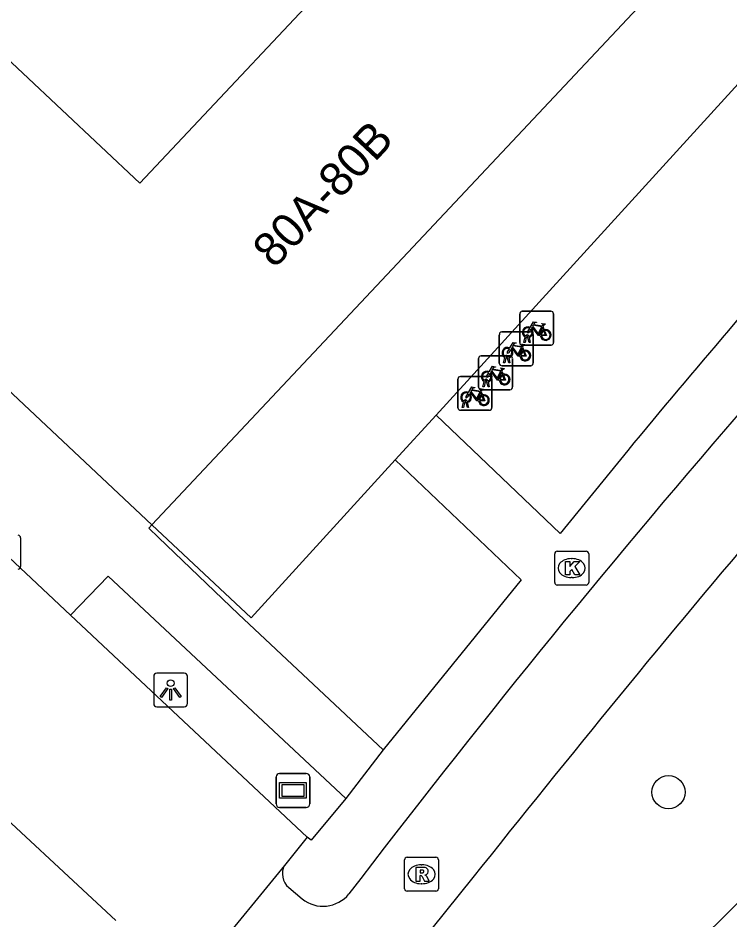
# Model space of a CAD drawing. Extents: x 159040 to 160094, y 381214 to 382518.
# Drawn here: x 159467.3 to 159488.3, y 381527.19 to 381553.81 of the extents above; entities that cross this region are included whole.
import ezdxf

# ---------------------------------------------------------------- set-up
doc = ezdxf.new("R2010")
doc.units = 0
for name, color, linetype in [('IMGEO_Boom', 7, 'Continuous'), ('IMGEO_Fietsenrek', 7, 'Continuous'), ('IMGEO_Fietspad_gesloten', 7, 'Continuous'), ('IMGEO_Groenvoorziening', 7, 'Continuous'), ('IMGEO_Kolk', 7, 'Continuous'), ('IMGEO_Lichtpunt', 7, 'Continuous'), ('IMGEO_Pand', 7, 'Continuous'), ('IMGEO_Pand_nummerreeks', 7, 'Continuous'), ('IMGEO_Rijbaan_lokaal_open', 7, 'Continuous'), ('IMGEO_Rijbaan_regionaal_gesloten', 7, 'Continuous'), ('IMGEO_Rioolput', 7, 'Continuous'), ('IMGEO_Straatnaambord', 7, 'Continuous'), ('IMGEO_Voetpad_open', 7, 'Continuous')]:
    doc.layers.add(name, color=color, linetype=linetype)

msp = doc.modelspace()

# ---------------------------------------------------------------- linework, layer by layer
at = {"layer": 'IMGEO_Boom'}
msp.add_circle((159486.484, 381530.962), 0.489, dxfattribs=at)
at = {"layer": 'IMGEO_Fietsenrek'}
for p, q in [((159482.094, 381544.228), (159482.094, 381545.069)), ((159482.094, 381545.069), (159482.094, 381544.228)), ((159482.169, 381545.153), (159483.01, 381545.153)), ((159483.01, 381545.153), (159482.169, 381545.153)), ((159483.094, 381545.078), (159483.094, 381544.237)), ((159483.094, 381544.237), (159483.094, 381545.078)), ((159482.781, 381544.702), (159482.817, 381544.607)), ((159481.494, 381543.621), (159481.494, 381544.462)), ((159481.494, 381544.462), (159481.494, 381543.621)), ((159481.569, 381544.546), (159482.41, 381544.546)), ((159482.41, 381544.546), (159481.569, 381544.546)), ((159482.221, 381544.237), (159482.26, 381544.397)), ((159482.332, 381544.409), (159482.331, 381544.413)), ((159482.363, 381544.42), (159482.364, 381544.413)), ((159482.494, 381544.471), (159482.494, 381543.63)), ((159482.494, 381543.63), (159482.494, 381544.471)), ((159483.019, 381544.153), (159482.178, 381544.153)), ((159482.178, 381544.153), (159483.019, 381544.153)), ((159482.255, 381544.237), (159482.221, 381544.237)), ((159482.29, 381544.385), (159482.255, 381544.237)), ((159482.373, 381544.237), (159482.339, 381544.379)), ((159482.371, 381544.383), (159482.406, 381544.237)), ((159482.406, 381544.237), (159482.373, 381544.237)), ((159482.181, 381544.095), (159482.217, 381544)), ((159480.883, 381542.915), (159480.883, 381543.756)), ((159480.883, 381543.756), (159480.883, 381542.915)), ((159480.958, 381543.84), (159481.799, 381543.84)), ((159481.799, 381543.84), (159480.958, 381543.84)), ((159481.621, 381543.63), (159481.66, 381543.79)), ((159481.655, 381543.63), (159481.621, 381543.63)), ((159481.69, 381543.778), (159481.655, 381543.63)), ((159481.732, 381543.802), (159481.731, 381543.806)), ((159481.773, 381543.63), (159481.739, 381543.772)), ((159481.763, 381543.813), (159481.764, 381543.806)), ((159481.771, 381543.776), (159481.806, 381543.63)), ((159481.806, 381543.63), (159481.773, 381543.63)), ((159481.883, 381543.765), (159481.883, 381542.924)), ((159481.883, 381542.924), (159481.883, 381543.765)), ((159481.57, 381543.389), (159481.606, 381543.294)), ((159482.419, 381543.546), (159481.578, 381543.546)), ((159481.578, 381543.546), (159482.419, 381543.546)), ((159480.273, 381542.306), (159480.273, 381543.147)), ((159480.273, 381543.147), (159480.273, 381542.306)), ((159480.348, 381543.231), (159481.189, 381543.231)), ((159481.189, 381543.231), (159480.348, 381543.231)), ((159481.01, 381542.924), (159481.049, 381543.084)), ((159481.079, 381543.072), (159481.044, 381542.924)), ((159481.121, 381543.096), (159481.12, 381543.1)), ((159481.162, 381542.924), (159481.128, 381543.066)), ((159481.152, 381543.107), (159481.153, 381543.1)), ((159481.16, 381543.07), (159481.195, 381542.924)), ((159481.273, 381543.156), (159481.273, 381542.315)), ((159481.273, 381542.315), (159481.273, 381543.156)), ((159481.808, 381542.84), (159480.967, 381542.84)), ((159480.967, 381542.84), (159481.808, 381542.84)), ((159481.044, 381542.924), (159481.01, 381542.924)), ((159481.195, 381542.924), (159481.162, 381542.924)), ((159480.96, 381542.78), (159480.996, 381542.685)), ((159480.4, 381542.315), (159480.439, 381542.475)), ((159480.434, 381542.315), (159480.4, 381542.315)), ((159480.469, 381542.463), (159480.434, 381542.315)), ((159480.511, 381542.487), (159480.51, 381542.491)), ((159480.552, 381542.315), (159480.518, 381542.457)), ((159480.542, 381542.498), (159480.543, 381542.491)), ((159480.55, 381542.461), (159480.585, 381542.315)), ((159480.585, 381542.315), (159480.552, 381542.315)), ((159481.198, 381542.231), (159480.357, 381542.231)), ((159480.357, 381542.231), (159481.198, 381542.231))]:
    msp.add_line(p, q, dxfattribs=at)
for points in [[(159482.428, 381544.627), (159482.376, 381544.537), (159482.336, 381544.512), (159482.337, 381544.559), (159482.392, 381544.653)], [(159482.407, 381544.679), (159482.502, 381544.843), (159482.588, 381544.829), (159482.59, 381544.82), (159482.534, 381544.809), (159482.507, 381544.764), (159482.763, 381544.723)], [(159482.703, 381544.435), (159482.653, 381544.435), (159482.462, 381544.686), (159482.443, 381544.654)], [(159482.75, 381544.698), (159482.493, 381544.739), (159482.476, 381544.71), (159482.643, 381544.49), (159482.75, 381544.698)], [(159482.798, 381544.6), (159482.768, 381544.677), (159482.659, 381544.459), (159482.702, 381544.459)], [(159482.763, 381544.723), (159482.788, 381544.772), (159482.782, 381544.776), (159482.759, 381544.78), (159482.747, 381544.787), (159482.746, 381544.79), (159482.748, 381544.795), (159482.843, 381544.78), (159482.845, 381544.77), (159482.835, 381544.757), (159482.823, 381544.751), (159482.809, 381544.757), (159482.781, 381544.702)], [(159482.732, 381544.459), (159482.852, 381544.458), (159482.808, 381544.572)], [(159482.828, 381544.579), (159482.883, 381544.434), (159482.733, 381544.434)], [(159481.807, 381544.072), (159481.902, 381544.236), (159481.988, 381544.222), (159481.99, 381544.213), (159481.934, 381544.202), (159481.907, 381544.157), (159482.163, 381544.116)], [(159482.15, 381544.091), (159481.893, 381544.132), (159481.876, 381544.103), (159482.043, 381543.883), (159482.15, 381544.091)], [(159482.163, 381544.116), (159482.188, 381544.165), (159482.182, 381544.169), (159482.159, 381544.173), (159482.147, 381544.18), (159482.146, 381544.183), (159482.148, 381544.188), (159482.243, 381544.173), (159482.245, 381544.163), (159482.235, 381544.15), (159482.223, 381544.144), (159482.209, 381544.15), (159482.181, 381544.095)], [(159481.828, 381544.02), (159481.776, 381543.93), (159481.736, 381543.905), (159481.737, 381543.952), (159481.792, 381544.046)], [(159482.103, 381543.828), (159482.053, 381543.828), (159481.862, 381544.079), (159481.843, 381544.047)], [(159482.198, 381543.993), (159482.168, 381544.07), (159482.059, 381543.852), (159482.102, 381543.852)], [(159482.132, 381543.852), (159482.252, 381543.851), (159482.208, 381543.965)], [(159482.228, 381543.972), (159482.283, 381543.827), (159482.133, 381543.827)], [(159481.217, 381543.314), (159481.165, 381543.224), (159481.125, 381543.199), (159481.126, 381543.246), (159481.181, 381543.34)], [(159481.196, 381543.366), (159481.291, 381543.53), (159481.377, 381543.516), (159481.379, 381543.507), (159481.323, 381543.496), (159481.296, 381543.451), (159481.552, 381543.41)], [(159481.492, 381543.122), (159481.442, 381543.122), (159481.251, 381543.373), (159481.232, 381543.341)], [(159481.539, 381543.385), (159481.282, 381543.426), (159481.265, 381543.397), (159481.432, 381543.177), (159481.539, 381543.385)], [(159481.587, 381543.287), (159481.557, 381543.364), (159481.448, 381543.146), (159481.491, 381543.146)], [(159481.552, 381543.41), (159481.577, 381543.459), (159481.571, 381543.463), (159481.548, 381543.467), (159481.536, 381543.474), (159481.535, 381543.477), (159481.537, 381543.482), (159481.632, 381543.467), (159481.634, 381543.457), (159481.624, 381543.444), (159481.612, 381543.438), (159481.598, 381543.444), (159481.57, 381543.389)], [(159481.521, 381543.146), (159481.641, 381543.145), (159481.597, 381543.259)], [(159481.617, 381543.266), (159481.672, 381543.121), (159481.522, 381543.121)], [(159480.586, 381542.757), (159480.681, 381542.921), (159480.767, 381542.907), (159480.769, 381542.898), (159480.713, 381542.887), (159480.686, 381542.842), (159480.942, 381542.801)], [(159480.929, 381542.776), (159480.672, 381542.817), (159480.655, 381542.788), (159480.822, 381542.568), (159480.929, 381542.776)], [(159480.942, 381542.801), (159480.967, 381542.85), (159480.961, 381542.854), (159480.938, 381542.858), (159480.926, 381542.865), (159480.925, 381542.868), (159480.927, 381542.873), (159481.022, 381542.858), (159481.024, 381542.848), (159481.014, 381542.835), (159481.002, 381542.829), (159480.988, 381542.835), (159480.96, 381542.78)], [(159480.607, 381542.705), (159480.555, 381542.615), (159480.515, 381542.59), (159480.516, 381542.637), (159480.571, 381542.731)], [(159480.882, 381542.513), (159480.832, 381542.513), (159480.641, 381542.764), (159480.622, 381542.732)], [(159480.977, 381542.678), (159480.947, 381542.755), (159480.838, 381542.537), (159480.881, 381542.537)], [(159480.911, 381542.537), (159481.031, 381542.536), (159480.987, 381542.65)], [(159481.007, 381542.657), (159481.062, 381542.512), (159480.912, 381542.512)]]:
    msp.add_lwpolyline(points, dxfattribs=at)
for centre, radius, start, end in [((159482.172, 381545.075), 0.0779, 92.4484, 184.2845), ((159482.172, 381545.075), 0.0779, 92.4484, 184.2845), ((159483.016, 381545.075), 0.0779, 2.4484, 94.2845), ((159483.016, 381545.075), 0.0779, 2.4484, 94.2845), ((159482.334, 381544.538), 0.159, 62.6766, 242.1369), ((159482.334, 381544.538), 0.129, 63.3192, 238.903), ((159482.334, 381544.538), 0.159, 283.5766, 46.6042), ((159481.572, 381544.468), 0.0779, 92.4484, 184.2845), ((159481.572, 381544.468), 0.0779, 92.4484, 184.2845), ((159482.314, 381544.409), 0.0499, 12.8025, 158.6934), ((159482.314, 381544.409), 0.0174, 12.8025, 163.4502), ((159482.334, 381544.538), 0.129, 253.415, 269.0204), ((159482.334, 381544.538), 0.129, 283.6043, 43.4302), ((159482.416, 381544.468), 0.0779, 2.4484, 94.2845), ((159482.416, 381544.468), 0.0779, 2.4484, 94.2845), ((159482.861, 381544.454), 0.159, 113.3408, 178.3217), ((159482.861, 381544.454), 0.159, 187.0065, 105.7708), ((159482.861, 381544.454), 0.129, 113.923, 177.9556), ((159482.861, 381544.454), 0.129, 188.6715, 104.5883), ((159482.172, 381544.231), 0.0779, 182.4484, 274.2845), ((159482.172, 381544.231), 0.0779, 182.4484, 274.2845), ((159482.334, 381544.538), 0.159, 253.9967, 271.7867), ((159483.016, 381544.231), 0.0779, 272.4484, 4.2845), ((159483.016, 381544.231), 0.0779, 272.4484, 4.2845), ((159481.734, 381543.931), 0.159, 62.6766, 242.1369), ((159481.734, 381543.931), 0.129, 63.3192, 238.903), ((159481.734, 381543.931), 0.129, 283.6043, 43.4302), ((159481.734, 381543.931), 0.159, 283.5766, 46.6042), ((159482.261, 381543.847), 0.159, 113.3408, 178.3217), ((159482.261, 381543.847), 0.159, 187.0065, 105.7708), ((159482.261, 381543.847), 0.129, 113.923, 177.9556), ((159482.261, 381543.847), 0.129, 188.6715, 104.5883), ((159480.961, 381543.762), 0.0779, 92.4484, 184.2845), ((159480.961, 381543.762), 0.0779, 92.4484, 184.2845), ((159481.572, 381543.624), 0.0779, 182.4484, 274.2845), ((159481.572, 381543.624), 0.0779, 182.4484, 274.2845), ((159481.714, 381543.802), 0.0499, 12.8025, 158.6934), ((159481.734, 381543.931), 0.159, 253.9967, 271.7867), ((159481.714, 381543.802), 0.0174, 12.8025, 163.4502), ((159481.734, 381543.931), 0.129, 253.415, 269.0204), ((159481.805, 381543.762), 0.0779, 2.4484, 94.2845), ((159481.805, 381543.762), 0.0779, 2.4484, 94.2845), ((159482.416, 381543.624), 0.0779, 272.4484, 4.2845), ((159482.416, 381543.624), 0.0779, 272.4484, 4.2845), ((159481.123, 381543.225), 0.159, 62.6766, 242.1369), ((159481.123, 381543.225), 0.129, 63.3192, 238.903), ((159481.123, 381543.225), 0.159, 283.5766, 46.6042), ((159480.351, 381543.153), 0.0779, 92.4484, 184.2845), ((159480.351, 381543.153), 0.0779, 92.4484, 184.2845), ((159481.103, 381543.096), 0.0499, 12.8025, 158.6934), ((159481.123, 381543.225), 0.159, 253.9967, 271.7867), ((159481.103, 381543.096), 0.0174, 12.8025, 163.4502), ((159481.123, 381543.225), 0.129, 253.415, 269.0204), ((159481.123, 381543.225), 0.129, 283.6043, 43.4302), ((159481.195, 381543.153), 0.0779, 2.4484, 94.2845), ((159481.195, 381543.153), 0.0779, 2.4484, 94.2845), ((159481.65, 381543.141), 0.159, 113.3408, 178.3217), ((159481.65, 381543.141), 0.159, 187.0065, 105.7708), ((159481.65, 381543.141), 0.129, 113.923, 177.9556), ((159481.65, 381543.141), 0.129, 188.6715, 104.5883), ((159480.961, 381542.918), 0.0779, 182.4484, 274.2845), ((159480.961, 381542.918), 0.0779, 182.4484, 274.2845), ((159481.805, 381542.918), 0.0779, 272.4484, 4.2845), ((159481.805, 381542.918), 0.0779, 272.4484, 4.2845), ((159480.513, 381542.616), 0.159, 62.6766, 242.1369), ((159480.513, 381542.616), 0.129, 63.3192, 238.903), ((159480.493, 381542.487), 0.0499, 12.8025, 158.6934), ((159480.513, 381542.616), 0.129, 283.6043, 43.4302), ((159480.513, 381542.616), 0.159, 283.5766, 46.6042), ((159481.04, 381542.532), 0.159, 113.3408, 178.3217), ((159481.04, 381542.532), 0.159, 187.0065, 105.7708), ((159481.04, 381542.532), 0.129, 113.923, 177.9556), ((159481.04, 381542.532), 0.129, 188.6715, 104.5883), ((159480.351, 381542.309), 0.0779, 182.4484, 274.2845), ((159480.351, 381542.309), 0.0779, 182.4484, 274.2845), ((159480.513, 381542.616), 0.159, 253.9967, 271.7867), ((159480.493, 381542.487), 0.0174, 12.8025, 163.4502), ((159480.513, 381542.616), 0.129, 253.415, 269.0204), ((159481.195, 381542.309), 0.0779, 272.4484, 4.2845), ((159481.195, 381542.309), 0.0779, 272.4484, 4.2845)]:
    msp.add_arc(centre, radius, start, end, dxfattribs=at)
at = {"layer": 'IMGEO_Fietspad_gesloten'}
for points in [[(159480.715, 381528.442), (159478.696, 381525.942), (159466.055, 381510.293)], [(159475.288, 381528.15), (159475.676, 381527.813)]]:
    msp.add_lwpolyline(points, dxfattribs=at)
for centre, radius, start, end in [((159714.564, 381347.031), 298.57, 135.70827, 142.7), ((159807.274, 381269.803), 416.575, 137.82976, 141.62035), ((159475.625, 381528.558), 0.53, 152.361, 230.4609), ((159476.293, 381528.592), 0.993, 231.6248, 320.5828)]:
    msp.add_arc(centre, radius, start, end, dxfattribs=at)
at = {"layer": 'IMGEO_Groenvoorziening'}
for points in [[(159494.82, 381558.774), (159479.629, 381542.092)], [(159478.425, 381540.77), (159474.176, 381536.104), (159471.246, 381538.856)]]:
    msp.add_lwpolyline(points, dxfattribs=at)
at = {"layer": 'IMGEO_Kolk'}
for p, q in [((159467.375, 381538.47), (159467.375, 381537.618)), ((159483.128, 381537.149), (159483.128, 381538.001)), ((159483.203, 381538.075), (159484.055, 381538.075)), ((159484.129, 381538.001), (159484.129, 381537.149)), ((159483.616, 381537.855), (159483.641, 381537.855)), ((159483.639, 381537.295), (159483.614, 381537.295)), ((159484.055, 381537.075), (159483.203, 381537.075))]:
    msp.add_line(p, q, dxfattribs=at)
for points in [[(159467.375, 381538.47), (159467.375, 381537.618)], [(159483.128, 381537.149), (159483.128, 381538.001)], [(159483.203, 381538.075), (159484.055, 381538.075)], [(159484.129, 381538.001), (159484.129, 381537.149)], [(159483.449, 381537.775), (159483.572, 381537.775), (159483.572, 381537.624), (159483.702, 381537.775), (159483.866, 381537.775), (159483.72, 381537.624), (159483.873, 381537.375), (159483.721, 381537.375), (159483.636, 381537.539), (159483.572, 381537.472), (159483.572, 381537.375), (159483.449, 381537.375), (159483.449, 381537.775)], [(159484.055, 381537.075), (159483.203, 381537.075)]]:
    msp.add_lwpolyline(points, dxfattribs=at)
for centre, start, end in [((159467.299, 381538.468), 1.552, 88.448), ((159467.299, 381538.468), 1.552, 88.448), ((159483.205, 381537.999), 91.552, 178.448), ((159483.205, 381537.999), 91.552, 178.448), ((159484.053, 381537.999), 1.552, 88.448), ((159484.053, 381537.999), 1.552, 88.448), ((159467.299, 381537.62), 271.552, 358.448), ((159467.299, 381537.62), 271.552, 358.448), ((159483.205, 381537.151), 181.552, 268.448), ((159483.205, 381537.151), 181.552, 268.448), ((159484.053, 381537.151), 271.552, 358.448), ((159484.053, 381537.151), 271.552, 358.448)]:
    msp.add_arc(centre, 0.0765, start, end, dxfattribs=at)
for centre, major_axis, ratio, start_param, end_param in [((159483.615, 381537.575), (-0.387, 0.002), 0.722429, 4.712389, 7.853982), ((159483.64, 381537.575), (-0.39, 0.002), 0.717154, 1.570796, 4.712389)]:
    msp.add_ellipse(centre, major_axis=major_axis, ratio=ratio, start_param=start_param, end_param=end_param, dxfattribs=at)
at = {"layer": 'IMGEO_Lichtpunt'}
for p, q in [((159471.302, 381534.383), (159471.302, 381533.576)), ((159471.302, 381534.383), (159471.302, 381533.576)), ((159472.204, 381534.478), (159471.396, 381534.478)), ((159472.204, 381534.478), (159471.396, 381534.478)), ((159472.298, 381533.576), (159472.298, 381534.383)), ((159472.298, 381533.576), (159472.298, 381534.383)), ((159471.396, 381533.482), (159472.204, 381533.482)), ((159471.396, 381533.482), (159472.204, 381533.482))]:
    msp.add_line(p, q, dxfattribs=at)
for points in [[(159471.676, 381534.047), (159471.715, 381534.019), (159471.527, 381533.757), (159471.489, 381533.784), (159471.676, 381534.047)], [(159471.888, 381534.019), (159471.926, 381534.046), (159472.113, 381533.784), (159472.074, 381533.756), (159471.888, 381534.019)], [(159471.778, 381533.999), (159471.825, 381533.999), (159471.825, 381533.677), (159471.778, 381533.677), (159471.778, 381533.999)]]:
    msp.add_lwpolyline(points, dxfattribs=at)
msp.add_circle((159471.801, 381534.181), 0.0994, dxfattribs=at)
for centre, start, end in [((159471.396, 381534.383), 90, 180), ((159471.396, 381534.383), 90, 180), ((159472.204, 381534.383), 0, 90), ((159472.204, 381534.383), 0, 90), ((159471.396, 381533.576), 180, 270), ((159471.396, 381533.576), 180, 270), ((159472.204, 381533.576), 270, 0), ((159472.204, 381533.576), 270, 360)]:
    msp.add_arc(centre, 0.0946, start, end, dxfattribs=at)
at = {"layer": 'IMGEO_Pand'}
for points in [[(159471.246, 381538.856), (159487.27, 381555.916), (159483.395, 381559.555), (159487.883, 381564.332), (159481.909, 381569.943)], [(159466.281, 381553.264), (159470.896, 381548.93), (159477.649, 381556.12), (159477.948, 381555.839), (159479.992, 381558.015), (159475.037, 381562.627)], [(159461.398, 381548.106), (159471.246, 381538.856)]]:
    msp.add_lwpolyline(points, dxfattribs=at)
at = {"layer": 'IMGEO_Rijbaan_lokaal_open'}
for points in [[(159468.846, 381536.185), (159466.875, 381538.044), (159466.685, 381538.22), (159458.784, 381545.549), (159453.733, 381550.451), (159453.52, 381550.648), (159446.812, 381556.846), (159440.803, 381562.65)], [(159468.846, 381536.185), (159475.828, 381529.637)], [(159470.189, 381527.178), (159465.844, 381531.211), (159465.756, 381531.298)], [(159475.828, 381529.637), (159475.156, 381528.804)], [(159475.156, 381528.804), (159472.991, 381526.144)]]:
    msp.add_lwpolyline(points, dxfattribs=at)
at = {"layer": 'IMGEO_Rijbaan_regionaal_gesloten'}
msp.add_lwpolyline([(159524.392, 381565.298), (159524.318, 381565.22), (159513.487, 381553.459), (159509.914, 381549.667), (159499.797, 381539.047), (159492.644, 381531.758), (159482.267, 381521.51), (159465.201, 381505.256), (159442.492, 381484.426), (159434.773, 381477.467), (159414.042, 381459.154), (159404.558, 381450.901), (159395.563, 381443.073), (159354.89, 381408.246), (159339.224, 381394.831), (159304.87, 381365.271), (159301.884, 381362.731)], dxfattribs=at)
at = {"layer": 'IMGEO_Rioolput'}
for p, q in [((159478.699, 381528.116), (159478.699, 381528.968)), ((159478.774, 381529.042), (159479.626, 381529.042)), ((159479.7, 381528.968), (159479.7, 381528.116)), ((159479.187, 381528.822), (159479.212, 381528.822)), ((159479.21, 381528.262), (159479.185, 381528.262)), ((159479.626, 381528.042), (159478.774, 381528.042))]:
    msp.add_line(p, q, dxfattribs=at)
for points in [[(159478.699, 381528.116), (159478.699, 381528.968)], [(159478.774, 381529.042), (159479.626, 381529.042)], [(159479.7, 381528.968), (159479.7, 381528.116)], [(159479.288, 381528.74), (159479.036, 381528.742), (159479.036, 381528.342)], [(159479.036, 381528.342), (159479.16, 381528.342), (159479.16, 381528.504), (159479.171, 381528.504)], [(159479.214, 381528.661), (159479.16, 381528.661), (159479.16, 381528.58)], [(159479.16, 381528.58), (159479.212, 381528.58)], [(159479.218, 381528.475), (159479.289, 381528.342), (159479.429, 381528.342), (159479.364, 381528.468)], [(159479.626, 381528.042), (159478.774, 381528.042)]]:
    msp.add_lwpolyline(points, dxfattribs=at)
for centre, radius, start, end in [((159478.776, 381528.966), 0.0765, 91.552, 178.448), ((159478.776, 381528.966), 0.0765, 91.552, 178.448), ((159479.624, 381528.966), 0.0765, 1.552, 88.448), ((159479.624, 381528.966), 0.0765, 1.552, 88.448), ((159479.287, 381528.63), 0.109, 350.3612, 89.416), ((159479.17, 381528.451), 0.0533, 26.0293, 88.6989), ((159479.196, 381528.769), 0.19, 274.7715, 282.9687), ((159479.22, 381528.565), 0.0964, 77.0061, 93.1865), ((159479.234, 381528.622), 0.0378, 276.6634, 79.6772), ((159479.285, 381528.63), 0.112, 277.5842, 350.9817), ((159479.269, 381528.415), 0.108, 29.5134, 73.7905), ((159478.776, 381528.118), 0.0765, 181.552, 268.448), ((159478.776, 381528.118), 0.0765, 181.552, 268.448), ((159479.624, 381528.118), 0.0765, 271.552, 358.448), ((159479.624, 381528.118), 0.0765, 271.552, 358.448)]:
    msp.add_arc(centre, radius, start, end, dxfattribs=at)
for centre, major_axis, ratio, start_param, end_param in [((159479.186, 381528.542), (-0.387, 0.002), 0.722429, 4.712389, 7.853982), ((159479.211, 381528.542), (-0.39, 0.002), 0.717154, 1.570796, 4.712389)]:
    msp.add_ellipse(centre, major_axis=major_axis, ratio=ratio, start_param=start_param, end_param=end_param, dxfattribs=at)
at = {"layer": 'IMGEO_Straatnaambord'}
for p, q in [((159474.912, 381530.615), (159474.912, 381531.415)), ((159474.912, 381531.415), (159474.912, 381530.615)), ((159475.012, 381531.515), (159475.802, 381531.515)), ((159475.802, 381531.515), (159475.012, 381531.515)), ((159475.902, 381531.415), (159475.902, 381530.615)), ((159475.902, 381530.615), (159475.902, 381531.415)), ((159475.802, 381530.515), (159475.012, 381530.515)), ((159475.012, 381530.515), (159475.802, 381530.515))]:
    msp.add_line(p, q, dxfattribs=at)
for points in [[(159475.013, 381531.247), (159475.801, 381531.247), (159475.801, 381530.783), (159475.013, 381530.783), (159475.013, 381531.247)], [(159475.078, 381531.182), (159475.078, 381530.848), (159475.736, 381530.848), (159475.736, 381531.182), (159475.078, 381531.182)]]:
    msp.add_lwpolyline(points, dxfattribs=at)
for centre, start, end in [((159475.012, 381531.415), 90, 180), ((159475.012, 381531.415), 90, 180), ((159475.802, 381531.415), 0, 90), ((159475.802, 381531.415), 360, 90), ((159475.012, 381530.615), 180, 270), ((159475.012, 381530.615), 180, 270), ((159475.802, 381530.615), 270, 0), ((159475.802, 381530.615), 270, 0)]:
    msp.add_arc(centre, 0.1, start, end, dxfattribs=at)
at = {"layer": 'IMGEO_Voetpad_open'}
for points in [[(159479.629, 381542.092), (159478.425, 381540.77)], [(159485.281, 381541.046), (159483.291, 381538.599), (159479.629, 381542.092)], [(159478.425, 381540.77), (159482.14, 381537.23), (159478.068, 381532.212)], [(159471.246, 381538.856), (159471.156, 381538.756), (159471.444, 381538.475), (159473.798, 381536.22), (159478.068, 381532.212)], [(159476.972, 381530.775), (159469.96, 381537.34), (159468.846, 381536.185)], [(159478.068, 381532.212), (159476.972, 381530.775)], [(159476.972, 381530.775), (159475.948, 381529.546), (159475.828, 381529.637)]]:
    msp.add_lwpolyline(points, dxfattribs=at)
msp.add_arc((159685.418, 381376.387), 259.167, 138.51157, 140.55482, dxfattribs=at)

# ---------------------------------------------------------------- texts
at = {"layer": 'IMGEO_Pand_nummerreeks'}
msp.add_text('80A-80B', height=1, rotation=46.7936, dxfattribs=at).set_placement((159474.863, 381546.389))

doc.saveas('drawing.dxf')
